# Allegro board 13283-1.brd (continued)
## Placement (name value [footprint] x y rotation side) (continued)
EC9704  SCD1U25V2KX-GP  [C402H22]  147.77 31.95 90 top
EC9705  SCD1U25V2KX-GP  [C402H22]  123.52 148.91 0 bottom
EC9707  SC1KP50V2KX-1GP  [C402H22]  62.43 96.84 180 top
EC9708  SCD1U25V2KX-GP  [C402H22]  108.28 2.99 0 top
EC9709  SC1KP50V2KX-1GP  [C402H22]  113.87 19.37 270 top
EC9710  SC1KP50V2KX-1GP  [C402H22]  118.06 33.6 180 top
EC9711  SC1KP50V2KX-1GP  [C402H22]  152.6 55.57 90 top
EC9712  SCD1U25V2KX-GP  [C402H22]  168.48 70.17 90 top
EC9713  SCD1U25V2KX-GP  [C402H22]  119.07 131.77 90 bottom
EC9714  SC1KP50V2KX-1GP  [C402H22]  119.2 115.51 270 top
EC9715  SCD1U25V2KX-GP  [C402H22]  148.03 96.33 0 top
EC9716  SCD1U25V2KX-GP  [C402H22]  55.19 92.52 270 top
EC9717  SCD1U25V2KX-GP  [C402H22]  86.73 125.76 180 bottom
EC9718  SC1U6D3V2KX-GP  [C402H22]  46.96 2.66 0 top
EC9719  SC1U6D3V2KX-GP  [C402H22]  50.98 2.66 0 top
EC9720  SC1U6D3V2KX-GP  [C402H22]  167.59 10.23 180 top
EC9721  SC1U6D3V2KX-GP  [C402H22]  187.98 7.47 180 bottom
EC9722  SC1U6D3V2KX-GP  [C402H22]  134.66 6.31 180 top
EC9723  SC1U6D3V2KX-GP  [C402H22]  195.91 71.57 90 top
EC9724  SC1U6D3V2KX-GP  [C402H22]  30.81 70.81 180 top
EC9725  SC1U6D3V2KX-GP  [C402H22]  195.27 83.63 270 bottom
EC9726  SC1U6D3V2KX-GP  [C402H22]  152.35 153.23 180 top
EC9727  SC1U6D3V2KX-GP  [C402H22]  193.58 110.21 90 bottom
EC9728  SC1U6D3V2KX-GP  [C402H22]  147.14 130.24 90 bottom
EC9729  SC1U6D3V2KX-GP  [C402H22]  148.79 153.23 0 bottom
EC9730  SC1U6D3V2KX-GP  [C402H22]  189.81 130.24 270 bottom
EC9731  SC1U6D3V2KX-GP  [C402H22]  176.73 69.54 90 bottom
EC9732  SC1U6D3V2KX-GP  [C402H22]  137.38 7.41 0 top
EC9733  SC1U6D3V2KX-GP  [C402H22]  104.43 9.09 0 bottom
EC9734  SC1U6D3V2KX-GP  [C402H22]  138.27 7.41 0 top
EC9735  SC1U6D3V2KX-GP  [C402H22]  35.13 68.75 0 top
EC9736  SC1U6D3V2KX-GP  [C402H22]  51.64 72.2 0 bottom
EC9737  SC1U6D3V2KX-GP  [C402H22]  45.67 35.53 180 top
EC9738  SC1U6D3V2KX-GP  [C402H22]  130.15 3.78 0 top
EC9739  SCD1U10V2KX-5GP  [C402H22]  33.12 20.92 180 top
EC9740  SCD1U25V2KX-GP  [C402H22]  115.39 132.02 180 top
EC9741  SCD1U25V2KX-GP  [C402H22]  158.82 100.65 90 top
EC9742  SCD1U25V2KX-GP  [C402H22]  139.77 113.35 180 top
EC9743  SCD1U10V2KX-5GP  [C402H22]  32.31 20.92 180 top
EC9744  SCD1U10V2KX-5GP  [C402H22]  31.49 20.92 180 top
EC9745  SC1KP50V2KX-1GP  [C402H22]  28.65 7.94 270 bottom
EC9747  SCD1U25V2KX-GP  [C402H22]  127.45 119.19 180 top
EC9748  SCD1U25V2KX-GP  [C402H22]  125.68 127.7 0 bottom
EC9749  SCD1U25V2KX-GP  [C402H22]  143.18 13.89 0 top
ED2901  AZ2025-01H-R7G-GP  [SOD-523-4H28]  23.49 8.41 90 top
ED2902  AZ2025-01H-R7G-GP  [SOD-523-4H28]  23.44 3.62 0 top
ED2903  AZ2025-01H-R7G-GP  [SOD-523-4H28]  18.87 2.99 90 top
ED2904  AZ2025-01H-R7G-GP  [SOD-523-4H28]  23.44 6.55 90 top
ED2905  AZ2025-01H-R7G-GP  [SOD-523-4H28]  23.49 10.22 90 top
F5201  POLYSW-1D1A24V-2-GP  [POLYSW-4633-UH63]  56.08 85.79 0 top
F5203  POLYSW-1D1A24V-GP-U  [POLYSW-4633-UH43]  31.13 74.23 270 top
F5401  POLYSW-1D1A6V-9-GP-U  [POLYSW-2114H30]  18.41 94.2 90 bottom
F6201  POLYSW-D5A6V-1-GP  [POLYSW-2114H50]  126.18 101.54 0 top
FAN1  ETY-CON3-8-GP  [3703K-Q03N-11L]  47.78 92.43 270 bottom
FAN261  APL5606AKI-TRG-GP  [SOIC8H69]  31.95 93.41 270 bottom
G701  GAP-OPEN  [CON2O-U]  114.25 101.92 90 top
GPU1  SUN-S3-XT-GP  [BGA631M23H82]  165.09 117.24 180 bottom
H1  HOLE335R115-GP  [HOLE335R115]  116.1 152.7 0 top
H2  HOLE335R115-GP  [HOLE335R115]  19.9 16.2 0 top
H3  HOLE335R115-GP  [HOLE335R115]  24.8 67.4 0 top
H4  HOLE256R115-GP  [HOLE256R115]  194.9 62.4 0 top
H5  HT85BE85R29-U-5-GP  [HT85BE85R29-U-5]  175.4 5.2 0 top
H6  HT85BE85R29-U-5-GP  [HT85BE85R29-U-5]  197.94 141.4 0 bottom
HDA27  ALC3234-CG-GP  [QFN48J6-G465H40]  35.63 10.74 270 top
HDD1  SKT-SATA7P-15P-159-GP  [127043HR022M25FZR]  198.74 23.03 270 bottom
HDMI1  SKT-HDMI23-97-GP  [SKT-HDMI23-188137]  4.05 86.2 90 bottom
HDT1  PAD-20P-127058-GP  [PAD-20P-127058]  59.76 70.81 270 top
HPMIC1  AUDIO-JK430-GP  [2SJ3080-036111F]  3.5 8.1 90 bottom
IOBD1  PTWO-CON16-2-GP  [196353-16021-3]  184.9 12.65 90 top
KB1  ACES-CON30-10-GP  [FL4S030HT6R300-DT]  183.8 93.86 270 top
KB2  ACES-CON30-10-GP  [FL4S030HT6R300-DT]  194.9 121.9 270 top
KBC24  NPCE285PA0DX-GP  [LQFP128H63]  169.89 29.9 270 top
KBLIT1  ACES-CON4-56-GP  [51575-00441-W01]  133.93 103.06 90 top
L3001  IND-4D7UH-242-GP  [L2520-D820H41]  30.1 40.5 180 bottom
L7504  BLM15BD121SN1D-GP  [L402H22]  163.4 105.22 180 top
L7601  BLM15BD121SN1D-GP  [L402H22]  160.09 103.19 90 bottom
L7603  BLM15BD121SN1D-GP  [L402H22]  164.21 101.97 0 bottom
L7703  BLM15BD121SN1D-GP  [L402H22]  184.22 125.42 0 bottom
L7704  BLM15AG221SN-GP  [L402H24]  176.48 121.35 0 top
L7705  BLM15BD121SN1D-GP  [L402H22]  184.22 127.45 180 bottom
L7706  0R0603-PAD-2-GP-U  [0R0603-PAD-1-U]  170.76 102.56 0 bottom
L7707  0R0603-PAD-2-GP-U  [0R0603-PAD-1-U]  167.71 105.48 180 top
LCD1  ACES-CON40-18-GP  [51540-04001-W01]  37.2 86.7 180 top
LIDSW1  S-5712ACDL1-M3T1U-GP  [SOT23-2D8-123H52]  2.8 73.6 270 top
LOM30  RTL8111G-CGT-1-GP-U1  [QFN32J4-G2D9-U1H36]  36.08 44.35 180 bottom
NOREF  -  []  4.9 -23.3 0 top
NOREF#2  -  []  0 110.96 270 top
NOREF#3  -  []  99.67 3.17 0 top
NOREF#4  *  [unnamed#2]  13.09 161.75 0 top
NOREF#5  *  [unnamed#2]  188.23 155.34 0 top
NOREF#6  -  []  95.96 50.61 0 top
NOREF#7  -  []  96.72 -3.49 0 top
NOREF#8  -  [unnamed#2]  62.23 116.65 0 top
NOREF#9  -  [unnamed#2]  5.32 163.87 0 top
NOREF#10  *  [unnamed#2]  139.65 96.08 0 top
NOREF#11  -  [unnamed#2]  198.19 53.13 0 top
NOREF#12  *  [unnamed#2]  169.36 80.08 0 top
NOREF#13  -  []  -14.81 138.55 0 top
NOREF#14  *  [unnamed#2]  28.78 5.78 0 top
NOREF#15  -  [unnamed#2]  192.53 3.75 0 top
NOREF#16  -  []  15.98 171.2 0 top
NOREF#17  *  [unnamed#2]  206.75 160.37 0 top
NOREF#18  -  [unnamed#2]  18.74 72.33 0 top
NOREF#19  -  []  213.89 52.6 90 top
NOREF#20  *  [unnamed#2]  209.43 10.58 0 top
NOREF#21  -  [unnamed#2]  167.7 154.4 0 top
NOREF#22  -  [unnamed#2]  206.77 165.96 0 top
NOREF#23  -  [unnamed#2]  189.28 164.18 0 top
NOREF#24  *  [unnamed#2]  194.38 7.05 0 top
NOREF#25  *  [unnamed#2]  48.46 24.2 0 top
NOREF#26  -  [unnamed#2]  206.66 -0.48 0 top
NOREF#27  -  [unnamed#2]  20.47 35.2 270 top
NOREF#28  -  []  4.9 -23.3 0 top
NOREF#29  -  []  4.9 -23.3 0 top
NOREF#30  *  [unnamed#2]  56.61 57.17 180 bottom
NOREF#31  -  []  93.04 2.86 180 bottom
NOREF#32  *  [unnamed#2]  188.29 155.39 180 bottom
NOREF#33  *  [unnamed#2]  28.27 37.28 0 bottom
NOREF#34  -  []  113.48 -3.49 180 bottom
NOREF#35  *  [unnamed#2]  24.51 4.11 180 bottom
NOREF#36  -  []  195.27 129.48 180 bottom
NOREF#37  *  [unnamed#2]  120.62 127.96 180 bottom
NOREF#38  *  [unnamed#2]  94.69 142.28 180 bottom
NOREF#39  -  []  66.42 50.16 180 bottom
NOREF#40  *  [unnamed#2]  206.75 160.37 180 bottom
NOREF#41  -  []  81.86 41.47 180 bottom
NOREF#42  *  [unnamed#2]  194.13 7.18 180 bottom
NOREF#43  *  [unnamed#2]  13.09 161.75 180 bottom
NOREF#44  *  [unnamed#2]  209.43 10.58 180 bottom
ODD1  SKT-SATA7P+6P-57-GP-U  [C185A1-11305-L-U]  201.55 76.9 270 bottom
PC4010  SCD47U25V3KX-1GP  [C603H36]  135.58 119.32 0 top
PC4201  SC1U50V5ZY-1-GP-U  [C805H58]  94.94 148.79 180 bottom
PC4202  SCD1U50V3KX-GP  [C603H36]  97.99 148.91 180 bottom
PC4203  SCD01U50V2KX-1GP  [C402H22]  87.2 150.69 90 bottom
PC4204  SCD01U50V2KX-1GP  [C402H22]  87.2 152.47 90 bottom
PC4205  SCD01U50V2KX-1GP  [C402H22]  87.2 151.58 90 bottom
PC4206  SC10U25V5KX-GP  [C805H56]  87.2 149.17 90 bottom
PC4208  SC1U25V3KX-1-GP  [C603H36]  96.09 145.99 180 bottom
PC4209  SCD01U50V2KX-1GP  [C402H22]  110.82 144.34 270 bottom
PC4210  SCD47U6D3V2KX-GP  [C402H22]  110.82 146.88 270 bottom
PC4401  SCD1U25V3KX-GP  [C603H36]  142.67 117.85 90 top
PC4402  SCD1U25V2KX-GP  [C402H22]  138.61 117.21 90 bottom
PC4403  SC1U25V3KX-1-GP  [C603H36]  137.46 118.36 90 bottom
PC4404  SC1U25V3KX-1-GP  [C603H36]  140 118.36 270 bottom
PC4406  SC10U25V5KX-GP  [C805H56]  130.25 125.8 270 bottom
PC4407  SC1U25V3KX-1-GP  [C603H36]  136.34 123.64 90 bottom
PC4408  SC4D7U25V5KX-GP  [C805H54]  130.25 123.89 270 bottom
PC4409  SCD1U50V3KX-GP  [C603H36]  130.25 125.54 90 top
PC4411  SCD047U25V2KX-GP  [C402H22]  134.44 122.12 0 top
PC4412  SCD01U50V2KX-1GP  [C402H22]  141.91 120.39 90 bottom
PC4413  SC3300P50V3KX-1GP  [C603H36]  135.58 121.73 180 top
PC4415  SC10U25V5KX-GP  [C805H56]  141.17 147.06 270 bottom
PC4416  SC10U25V5KX-GP  [C805H56]  141.17 145.23 270 bottom
PC4417  SC10U25V5KX-GP  [C805H56]  141.17 147.39 90 top
PC4418  SC10U25V5KX-GP  [C805H56]  141.17 149.29 90 top
PC4419  SCD1U50V3KX-GP  [C603H36]  141.27 148.71 270 bottom
PC4420  SCD1U25V2KX-GP  [C402H22]  140.28 125.42 180 bottom
PC4421  SCD1U25V2KX-GP  [C402H22]  140.79 126.69 270 bottom
PC4422  SC220P50V2JN-3GP  [C402H22]  141.91 122.17 90 bottom
PC4423  SCD1U25V2KX-GP  [C402H22]  141.17 125.42 180 bottom
PC4425  SCD01U50V2KX-1GP  [C402H22]  135.43 115.56 0 top
PC4426  SC10U25V5KX-GP  [C805H56]  130.25 123.89 90 top
PC4434  SC1U25V3KX-1-GP  [C603H36]  121.61 143.2 0 bottom
PC4501  SC18P50V2JN-1-GP  [C402H22]  130.12 44.14 180 top
PC4502  SC18P50V2JN-1-GP  [C402H22]  131.9 44.14 180 top
PC4510  SCD1U10V2KX-5GP  [C402H22]  120.09 10.61 90 bottom
PC4511  SCD1U50V3KX-GP  [C603H36]  123.64 30.93 90 top
PC4512  SC4D7U25V5KX-GP  [C805H54]  123.64 32.58 90 top
PC4513  SCD1U50V3KX-GP  [C603H36]  126.69 39.57 270 top
PC4514  SC560P50V-GP  [C603]  128.98 29.76 180 top
PC4515  SC4D7U6D3V3KX-GP  [C603H36]  132.15 35.63 0 top
PC4516  SC4D7U6D3V3KX-GP  [C603H36]  135.84 37.91 90 top
PC4517  SC10U25V5KX-GP  [C805H56]  128.01 36.01 0 top
PC4518  SCD1U50V3KX-GP  [C603H36]  129.56 36.14 0 top
PC4519  SCD1U50V3KX-GP  [C603H36]  135.96 39.31 270 top
PC4520  SC1U50V3KX-GP  [C603H32]  133.8 35.63 180 bottom
PC4521  SC560P50V-GP  [C603]  130.88 29.76 180 top
PC4523  SC10U25V5KX-GP  [C805H56]  136.73 32.33 270 top
PC4524  SCD1U50V3KX-GP  [C603H36]  136.47 30.68 270 top
PC4525  SCD1U10V2KX-5GP  [C402H22]  139.27 10.36 270 bottom
PC4526  SC22P50V2JN-4GP  [C402H22]  127.45 44.14 0 top
PC4527  SC22P50V2JN-4GP  [C402H22]  134.95 43.88 270 top
PC4528  SC1U10V2KX-1GP  [C402H22]  135.33 41.72 0 top
PC4601  SC1KP50V2KX-1GP  [C402H22]  108.79 134.82 270 top
PC4603  SC2D2U10V3KX-1GP  [C603H36]  105.48 133.55 180 top
PC4604  SC2D2U10V3KX-1GP  [C603H36]  112.34 138.68 0 bottom
PC4605  SC100P50V2JN-3GP  [C402H22]  111.2 135.7 180 bottom
PC4606  SC47P50V2JN-3GP  [C402H22]  112.09 136.59 0 bottom
PC4609  SC68P50V2JN-1GP  [C402H22]  100.91 138.24 0 top
PC4610  SCD1U10V2KX-5GP  [C402H22]  113.48 135.32 270 bottom
PC4611  SC100P50V2JN-3GP  [C402H22]  101.8 135.7 0 bottom
PC4612  SCD1U10V2KX-5GP  [C402H22]  100.91 136.47 0 bottom
PC4613  SCD1U10V2KX-5GP  [C402H22]  107.39 137.99 0 top
PC4617  SCD1U10V2KX-5GP  [C402H22]  106.5 137.99 0 top
PC4618  SC1U6D3V2ZY-GP  [C402H22]  104.72 137.99 0 top
PC4620  SCD1U10V2KX-4GP  [C402H20]  101.29 138.63 90 bottom
PC4621  SCD1U10V2KX-5GP  [C402H22]  101.29 139.51 90 bottom
PC4622  SCD1U10V2KX-4GP  [C402H20]  108.15 141.67 180 top
PC4623  SC1U25V3KX-1-GP  [C603H36]  117.12 123.84 180 bottom
PC4625  SC1U25V3KX-1-GP  [C603H36]  119.73 118.53 180 bottom
PC4701  SCD1U10V2KX-4GP  [C402H20]  101.29 134.31 270 top
PC4702  SCD1U10V2KX-4GP  [C402H20]  111.2 133.93 180 top
PC4703  SCD1U10V2KX-4GP  [C402H20]  112.09 133.93 180 top
PC4704  SCD1U10V2KX-4GP  [C402H20]  101.29 133.42 270 top
PC4713  SC10U25V5KX-GP  [C805H56]  94.56 129.86 270 bottom
PC4715  SC10U25V5KX-GP  [C805H56]  94.56 129.28 90 top
PC4716  SC10U25V5KX-GP  [C805H56]  110.44 127.83 90 bottom
PC4717  SC10U25V5KX-GP  [C805H56]  110.44 126.03 90 bottom
PC4718  SC10U25V5KX-GP  [C805H56]  110.44 127.83 270 top
PC4719  SC10U25V5KX-GP  [C805H56]  94.56 127.96 270 bottom
PC4720  SCD1U50V3KX-GP  [C603H36]  94.56 127.7 90 top
PC4721  SC10U25V5KX-GP  [C805H56]  110.44 126.03 270 top
PC4722  SCD1U50V3KX-GP  [C603H36]  110.44 124.48 90 bottom
PC4734  SCD1U50V3KX-GP  [C603H36]  107.01 129.48 0 bottom
PC4736  SCD1U50V3KX-GP  [C603H36]  103.71 129.23 0 bottom
PC4742  SC3300P50V3KX-1GP  [C603H36]  100.4 120.21 0 bottom
PC4743  SC3300P50V3KX-1GP  [C603H36]  104.59 117.29 0 bottom
PC4827  SCD1U50V3KX-GP  [C603H36]  161.62 72.97 0 bottom
PC4828  SC4D7U25V5KX-GP  [C805H54]  163.27 72.97 0 bottom
PC4829  SC1U10V2KX-1GP  [C402H22]  171.02 77.03 90 top
PC4830  SC10U25V5KX-GP  [C805H56]  165.17 72.97 0 bottom
PC4831  SC1KP50V2KX-1GP  [C402H22]  175.71 74.49 90 top
PC4832  SC18P50V2JN-1-GP  [C402H22]  175.71 77.16 270 top
PC4833  SCD1U50V3KX-GP  [C603H36]  167.46 74.62 90 bottom
PC4834  SCD1U10V2KX-4GP  [C402H20]  139.9 75.89 0 bottom
PC4838  SC560P50V-GP  [C603]  159.2 74.62 90 top
PC4901  SC1U10V3KX-3GP  [C603H36]  102.46 19.04 180 top
PC4902  SCD01U16V2KX-3GP  [C402H22]  104.59 19.75 180 top
PC4903  SCD1U10V2KX-4GP  [C402H20]  105.48 19.75 180 top
PC4904  SC1U10V3KX-3GP  [C603H36]  106.75 14.6 0 bottom
PC4906  SCD1U10V2KX-5GP  [C402H22]  102.44 11 0 top
PC4909  SC4D7U25V5KX-GP  [C805H54]  96.34 15.44 0 bottom
PC4911  SC4D7U25V5KX-GP  [C805H54]  98.24 15.44 180 top
PC4912  SC10U25V5KX-GP  [C805H56]  100.15 15.44 0 bottom
PC4913  SCD1U50V3KX-GP  [C603H36]  96.59 15.44 0 top
PC4914  SC4D7U25V5KX-GP  [C805H54]  98.24 15.44 0 bottom
PC4915  SCD1U10V2KX-4GP  [C402H20]  110.18 16.71 90 top
PC4916  SC10U6D3V3MX-GP  [C603H38]  109.93 15.31 90 top
PC4917  SC10U6D3V3MX-GP  [C603H38]  109.93 13.4 90 top
PC4918  SCD22U10V2KX-1GP  [C402H22]  107.39 17.59 90 top
PC4919  SCD1U50V3KX-GP  [C603H36]  100.4 14.55 90 top
PC4920  SC4D7U6D3V3KX-GP  [C603H36]  79.47 14.25 0 top
PC4921  SCD1U10V2KX-4GP  [C402H20]  80.86 14.25 0 top
PC4922  SC330P50V2KX-3GP  [C402H22]  94.51 18.15 270 bottom
PC4923  SC22U6D3V5MX-2GP  [C805H58]  79.7 12.77 180 bottom
PC4924  SC22U6D3V5MX-2GP  [C805H58]  77.8 12.77 180 bottom
PC4925  SC22U6D3V5MX-2GP  [C805H58]  81.61 12.77 180 bottom
PC4926  SC22U6D3V5MX-2GP  [C805H58]  83.51 12.77 180 bottom
PC5005  SC1U10V2KX-1GP  [C402H22]  160.86 64.58 0 bottom
PC5010  SC10U6D3V3MX-GP  [C603H38]  148.66 63.7 0 bottom
PC5011  SC10U6D3V3MX-GP  [C603H38]  165.17 58.62 180 bottom
PC5012  SC10U6D3V3MX-GP  [C603H38]  147.27 63.7 0 bottom
PC5013  SC1U6D3V2KX-GP  [C402H22]  165.17 61.92 0 bottom
PC5014  SC22P50V2JN-4GP  [C402H22]  165.17 63.7 180 bottom
PC5015  SC10U6D3V3MX-GP  [C603H38]  166.57 58.62 180 bottom
PC8202  SC2D2U10V3KX-1GP  [C603H36]  152.98 86.81 0 top
PC8203  SC2D2U10V3KX-1GP  [C603H36]  147.01 82.36 0 top
PC8205  SC1U25V3KX-1-GP  [C603H36]  153.49 95.7 180 top
PC8208  SC22P50V2JN-4GP  [C402H22]  147.62 93.67 180 top
PC8209  SC270P50V2JN-2GP  [C402H22]  148.92 93.67 0 top
PC8211  SCD1U10V2KX-4GP  [C402H20]  146.73 93.67 0 top
PC8213  SC1KP50V2KX-1GP  [C402H22]  150.31 82.24 270 top
PC8214  SCD1U10V2KX-4GP  [C402H20]  143.71 86.3 180 bottom
PC8215  14KR2F-GP  [R402H16]  143.33 86.81 270 top
PC8216  SC1U6D3V2ZY-GP  [C402H22]  143.2 91.25 270 top
PC8217  SCD1U10V2KX-4GP  [C402H20]  141.93 90.75 180 top
PC8218  SCD1U10V2KX-4GP  [C402H20]  144.98 93.29 270 top
PC8219  SCD1U10V2KX-4GP  [C402H20]  150.31 83.13 270 top
PC8220  SC10U25V5KX-GP  [C805H56]  158.11 89.6 180 bottom
PC8221  SC10U25V5KX-GP  [C805H56]  156.26 89.6 180 bottom
PC8222  SC10U25V5KX-GP  [C805H56]  154.4 89.6 180 bottom
PC8224  SCD01U50V2KX-1GP  [C402H22]  159.46 89.48 180 bottom
PC8230  SCD1U50V3KX-GP  [C603H36]  154.25 90.11 0 top
PC8232  SC3300P50V3KX-1GP  [C603H36]  162.25 81.86 90 bottom
PC8234  SCD1U10V2KX-4GP  [C402H20]  151.08 93.29 90 top
PC8236  SCD1U10V2KX-4GP  [C402H20]  152.35 95.45 0 top
PC8321  SC10U6D3V3MX-GP  [C603H38]  168.35 57.22 0 bottom
PC8322  SCD01U50V2KX-1GP  [C402H22]  168.86 50.23 180 bottom
PC8323  SC10U6D3V3MX-GP  [C603H38]  162.84 56.41 270 bottom
PC8324  SCD1U10V2KX-5GP  [C402H22]  187.02 112.59 0 bottom
PD4201  P6SBMJ24APT-GP  [D5436AKH97]  100.4 152.57 90 bottom
PD4203  DA3X101F0L-1-GP  [SOT23-2D8-312H56]  118.06 145.74 270 bottom
PD4204  PESD24VS2UT-GP  [SOT-23-10H44]  108.79 152.6 90 top
PD4302  SMF18AT1G-GP  [SOD123FLAKH40]  138.22 143.63 0 bottom
PD4401  SD103AWS-1-GP  [SOD323AKH42]  136.85 125.29 90 bottom
PD4404  1N4148WS-7-F-GP  [SOD323AKH42]  118.44 133.55 270 bottom
PD4505  MMPZ5231BPT-GP  [SOD-323-1UH40]  122.5 37.41 180 top
PD8201  RB551V30-GP  [SOD323AKH38]  149.68 79.57 270 top
PD8307  RB551V30-1-GP  [SOD323AKH44]  169.49 47.57 90 bottom
PD8308  RB551V30-GP  [SOD323AKH38]  190.32 115.77 90 bottom
PG4153  GAP-CLOSE-PWR-3-GP  [GAP-CLOSE-PWR-3]  120.47 14.93 180 bottom
PG4402  GAP-CLOSE-PWR-3-GP  [GAP-CLOSE-PWR-3]  91.51 141.42 0 bottom
PG4403  GAP-CLOSE-PWR-3-GP  [GAP-CLOSE-PWR-3]  91.51 140.15 0 bottom
PG4407  GAP-CLOSE-PWR-3-GP  [GAP-CLOSE-PWR-3]  145.08 122.04 0 top
PG4408  GAP-CLOSE-PWR-3-GP  [GAP-CLOSE-PWR-3]  145.08 121.02 0 top
PG4409  GAP-CLOSE-PWR-3-GP  [GAP-CLOSE-PWR-3]  132.53 142.94 180 bottom
PG4410  GAP-CLOSE-PWR-3-GP  [GAP-CLOSE-PWR-3]  132.53 144.47 180 bottom
PG4411  GAP-CLOSE-PWR-3-GP  [GAP-CLOSE-PWR-3]  139.39 124.02 90 bottom
PG4412  GAP-CLOSE-PWR-3-GP  [GAP-CLOSE-PWR-3]  126.69 125.8 0 bottom
PG4413  GAP-CLOSE-PWR-3-GP  [GAP-CLOSE-PWR-3]  126.69 125.04 0 bottom
PG4414  GAP-CLOSE-PWR-3-GP  [GAP-CLOSE-PWR-3]  126.69 124.27 0 bottom
PG4415  GAP-CLOSE-PWR-3-GP  [GAP-CLOSE-PWR-3]  126.69 123.51 0 bottom
PG4502  GAP-CLOSE-PWR-3-GP  [GAP-CLOSE-PWR-3]  119.33 30.68 180 top
PG4503  GAP-CLOSE-PWR-3-GP  [GAP-CLOSE-PWR-3]  119.33 31.44 180 top
PG4504  GAP-CLOSE-PWR-3-GP  [GAP-CLOSE-PWR-3]  119.33 32.2 180 top
PG4505  GAP-CLOSE-PWR-3-GP  [GAP-CLOSE-PWR-3]  119.33 32.96 180 top
PG4511  GAP-CLOSE-PWR-3-GP  [GAP-CLOSE-PWR-3]  136.34 10.1 90 bottom
PG4512  GAP-CLOSE-PWR-3-GP  [GAP-CLOSE-PWR-3]  135.58 10.1 90 bottom
PG4513  GAP-CLOSE-PWR-3-GP  [GAP-CLOSE-PWR-3]  122.12 10.36 270 bottom
PG4514  GAP-CLOSE-PWR-3-GP  [GAP-CLOSE-PWR-3]  137.11 10.1 90 bottom
PG4515  GAP-CLOSE-PWR-3-GP  [GAP-CLOSE-PWR-3]  140.41 30.42 0 top
PG4516  GAP-CLOSE-PWR-3-GP  [GAP-CLOSE-PWR-3]  140.41 31.18 0 top
PG4517  GAP-CLOSE-PWR-3-GP  [GAP-CLOSE-PWR-3]  140.41 31.95 0 top
PG4518  GAP-CLOSE-PWR-3-GP  [GAP-CLOSE-PWR-3]  140.41 32.71 0 top
PG4519  GAP-CLOSE-PWR-3-GP  [GAP-CLOSE-PWR-3]  140.41 33.47 0 top
PG4520  GAP-CLOSE-PWR-3-GP  [GAP-CLOSE-PWR-3]  140.41 34.23 0 top
PG4521  GAP-CLOSE-PWR-3-GP  [GAP-CLOSE-PWR-3]  140.41 34.99 0 top
PG4522  GAP-CLOSE-PWR-3-GP  [GAP-CLOSE-PWR-3]  122.88 10.36 270 bottom
PG4523  GAP-CLOSE-PWR-3-GP  [GAP-CLOSE-PWR-3]  123.64 10.36 270 bottom
PG4524  GAP-CLOSE-PWR-3-GP  [GAP-CLOSE-PWR-3]  132.53 10.1 90 bottom
PG4525  GAP-CLOSE-PWR-3-GP  [GAP-CLOSE-PWR-3]  124.41 10.36 270 bottom
PG4526  GAP-CLOSE-PWR-3-GP  [GAP-CLOSE-PWR-3]  125.17 10.36 270 bottom
PG4527  GAP-CLOSE-PWR-3-GP  [GAP-CLOSE-PWR-3]  131.77 10.1 90 bottom
PG4528  GAP-CLOSE-PWR-3-GP  [GAP-CLOSE-PWR-3]  133.3 10.1 90 bottom
PG4529  GAP-CLOSE-PWR-3-GP  [GAP-CLOSE-PWR-3]  134.06 10.1 90 bottom
PG4530  GAP-CLOSE-PWR-3-GP  [GAP-CLOSE-PWR-3]  125.93 10.36 270 bottom
PG4531  GAP-CLOSE-PWR-3-GP  [GAP-CLOSE-PWR-3]  134.82 10.1 90 bottom
PG4532  GAP-CLOSE-PWR-3-GP  [GAP-CLOSE-PWR-3]  137.74 14.67 0 bottom
PG4535  GAP-CLOSE-PWR-3-GP  [GAP-CLOSE-PWR-3]  137.87 10.1 90 bottom
PG4701  GAP-CLOSE-PWR-3-GP  [GAP-CLOSE-PWR-3]  95.58 117.04 90 bottom
PG4702  GAP-CLOSE-PWR-3-GP  [GAP-CLOSE-PWR-3]  95.58 114.75 270 bottom
PG4703  GAP-CLOSE-PWR-3-GP  [GAP-CLOSE-PWR-3]  89.61 126.81 180 bottom
PG4704  GAP-CLOSE-PWR-3-GP  [GAP-CLOSE-PWR-3]  89.61 127.58 180 bottom
PG4707  GAP-CLOSE-PWR-3-GP  [GAP-CLOSE-PWR-3]  89.61 129.86 180 bottom
PG4708  GAP-CLOSE-PWR-3-GP  [GAP-CLOSE-PWR-3]  89.61 130.62 180 bottom
PG4709  GAP-CLOSE-PWR-3-GP  [GAP-CLOSE-PWR-3]  89.61 129.1 180 bottom
PG4710  GAP-CLOSE-PWR-3-GP  [GAP-CLOSE-PWR-3]  89.61 128.34 180 bottom
PG4711  GAP-CLOSE-PWR-3-GP  [GAP-CLOSE-PWR-3]  114.63 126.31 0 top
PG4712  GAP-CLOSE-PWR-3-GP  [GAP-CLOSE-PWR-3]  114.63 125.54 0 top
PG4716  GAP-CLOSE-PWR-3-GP  [GAP-CLOSE-PWR-3]  114.63 124.78 0 top
PG4717  GAP-CLOSE-PWR-3-GP  [GAP-CLOSE-PWR-3]  114.63 127.83 0 top
PG4718  GAP-CLOSE-PWR-3-GP  [GAP-CLOSE-PWR-3]  114.63 127.07 0 top
PG4719  GAP-CLOSE-PWR-3-GP  [GAP-CLOSE-PWR-3]  109.42 111.57 270 bottom
PG4720  GAP-CLOSE-PWR-3-GP  [GAP-CLOSE-PWR-3]  109.42 113.86 90 bottom
PG4824  GAP-CLOSE-PWR-3-GP  [GAP-CLOSE-PWR-3]  137.49 72.84 0 bottom
PG4825  GAP-CLOSE-PWR-3-GP  [GAP-CLOSE-PWR-3]  137.49 73.6 0 bottom
PG4826  GAP-CLOSE-PWR-3-GP  [GAP-CLOSE-PWR-3]  137.49 74.36 0 bottom
PG4827  GAP-CLOSE-PWR-3-GP  [GAP-CLOSE-PWR-3]  165.05 70.93 0 bottom
PG4828  GAP-CLOSE-PWR-3-GP  [GAP-CLOSE-PWR-3]  137.49 75.13 0 bottom
PG4830  GAP-CLOSE-PWR-3-GP  [GAP-CLOSE-PWR-3]  137.49 71.32 0 bottom
PG4831  GAP-CLOSE-PWR-3-GP  [GAP-CLOSE-PWR-3]  137.49 72.08 0 bottom
PG4832  GAP-CLOSE-PWR-3-GP  [GAP-CLOSE-PWR-3]  141.3 75.89 270 bottom
PG4834  GAP-CLOSE-PWR-3-GP  [GAP-CLOSE-PWR-3]  165.05 68.65 0 bottom
PG4837  GAP-CLOSE-PWR-3-GP  [GAP-CLOSE-PWR-3]  165.05 69.41 0 bottom
PG4838  GAP-CLOSE-PWR-3-GP  [GAP-CLOSE-PWR-3]  165.05 70.17 0 bottom
PG4901  GAP-CLOSE-PWR-3-GP  [GAP-CLOSE-PWR-3]  109.55 17.98 270 top
PG4902  GAP-CLOSE-PWR-3-GP  [GAP-CLOSE-PWR-3]  108.79 17.98 270 top
PG4903  GAP-CLOSE-PWR-3-GP  [GAP-CLOSE-PWR-3]  97.1 11.24 270 top
PG4904  GAP-CLOSE-PWR-3-GP  [GAP-CLOSE-PWR-3]  97.86 11.24 270 top
PG4905  GAP-CLOSE-PWR-3-GP  [GAP-CLOSE-PWR-3]  98.63 11.24 270 top
PG4906  GAP-CLOSE-PWR-3-GP  [GAP-CLOSE-PWR-3]  96.34 11.24 270 top
PG4907  GAP-CLOSE-PWR-3-GP  [GAP-CLOSE-PWR-3]  76.65 13.66 0 bottom
PG4908  GAP-CLOSE-PWR-3-GP  [GAP-CLOSE-PWR-3]  81.48 18.61 270 top
PG4909  GAP-CLOSE-PWR-3-GP  [GAP-CLOSE-PWR-3]  80.72 18.61 270 top
PG4910  GAP-CLOSE-PWR-3-GP  [GAP-CLOSE-PWR-3]  79.96 18.61 270 top
PG4911  GAP-CLOSE-PWR-3-GP  [GAP-CLOSE-PWR-3]  83 18.61 270 top
PG4913  GAP-CLOSE-PWR-3-GP  [GAP-CLOSE-PWR-3]  76.91 18.61 270 top
PG4914  GAP-CLOSE-PWR-3-GP  [GAP-CLOSE-PWR-3]  77.67 18.61 270 top
PG4915  GAP-CLOSE-PWR-3-GP  [GAP-CLOSE-PWR-3]  78.43 18.61 270 top
PG4916  GAP-CLOSE-PWR-3-GP  [GAP-CLOSE-PWR-3]  79.19 18.61 270 top
PG4917  GAP-CLOSE-PWR-3-GP  [GAP-CLOSE-PWR-3]  82.24 18.61 270 top
PG4918  GAP-CLOSE-PWR-3-GP  [GAP-CLOSE-PWR-3]  83.77 18.61 270 top
PG4919  GAP-CLOSE-PWR-3-GP  [GAP-CLOSE-PWR-3]  84.53 18.61 270 top
PG5009  GAP-CLOSE-PWR-3-GP  [GAP-CLOSE-PWR-3]  168.09 59.5 180 bottom
PG5010  GAP-CLOSE-PWR-3-GP  [GAP-CLOSE-PWR-3]  146.12 59.63 180 bottom
PG5011  GAP-CLOSE-PWR-3-GP  [GAP-CLOSE-PWR-3]  146.12 60.39 180 bottom
PG5012  GAP-CLOSE-PWR-3-GP  [GAP-CLOSE-PWR-3]  146.12 61.16 180 bottom
PG5013  GAP-CLOSE-PWR-3-GP  [GAP-CLOSE-PWR-3]  146.12 61.92 180 bottom
PG5014  GAP-CLOSE-PWR-3-GP  [GAP-CLOSE-PWR-3]  168.09 60.27 180 bottom
PG8203  GAP-CLOSE-PWR-3-GP  [GAP-CLOSE-PWR-3]  157.93 94.68 90 bottom
PG8204  GAP-CLOSE-PWR-3-GP  [GAP-CLOSE-PWR-3]  158.7 94.68 90 bottom
PG8205  GAP-CLOSE-PWR-3-GP  [GAP-CLOSE-PWR-3]  159.46 94.68 90 bottom
PG8206  GAP-CLOSE-PWR-3-GP  [GAP-CLOSE-PWR-3]  154.12 94.68 90 bottom
PG8207  GAP-CLOSE-PWR-3-GP  [GAP-CLOSE-PWR-3]  154.89 94.68 90 bottom
PG8208  GAP-CLOSE-PWR-3-GP  [GAP-CLOSE-PWR-3]  155.65 94.68 90 bottom
PG8209  GAP-CLOSE-PWR-3-GP  [GAP-CLOSE-PWR-3]  156.41 94.68 90 bottom
PG8210  GAP-CLOSE-PWR-3-GP  [GAP-CLOSE-PWR-3]  157.17 94.68 90 bottom
PG8219  GAP-CLOSE-PWR-3-GP  [GAP-CLOSE-PWR-3]  171.9 88.84 180 bottom
PG8220  GAP-CLOSE-PWR-3-GP  [GAP-CLOSE-PWR-3]  174.19 88.84 0 bottom
PG8316  GAP-CLOSE-PWR-3-GP  [GAP-CLOSE-PWR-3]  142.44 104.59 0 bottom
PG8317  GAP-CLOSE-PWR-3-GP  [GAP-CLOSE-PWR-3]  144.35 101.29 0 bottom
PG8318  GAP-CLOSE-PWR-3-GP  [GAP-CLOSE-PWR-3]  144.35 100.53 0 bottom
PG8319  GAP-CLOSE-PWR-3-GP  [GAP-CLOSE-PWR-3]  144.35 99.76 0 bottom
PL4401  IND-5D6UH-45-GP  [L686647H119]  130.35 137.15 90 bottom
PL4501  IND-3D3UH-57GP  [L736630H119]  124.53 23.31 0 bottom
PL4502  IND-2D2UH-46-GP-U  [L736630-MH119]  135.71 23.44 180 bottom
PL4701  IND-D36UH-35-GP  [L7066-1830-UH158]  95.58 115.89 180 bottom
PL4702  IND-D36UH-35-GP  [L7066-1830-UH158]  109.42 112.72 180 bottom
PL4802  IND-2D2UH-46-GP-U  [L736630-MH119]  150.7 72.59 90 bottom
PL4902  COIL-D68UH-5-GP  [L736630H119]  89.1 14.72 90 bottom
PL5002  IND-2D2UH-46-GP-U  [L736630-MH119]  154.25 60.39 90 bottom
PL8201  IND-D36UH-35-GP  [L7066-1830-UH158]  173.05 88.84 270 bottom
PQ4201  FDV301N-NL-GP  [SOT23DGS2D4H44]  112.47 145.74 90 top
PQ4202  CH3904PT-GP  [SOT23CBE2D6H46]  113.87 145.86 270 bottom
PQ4203  2N7002KDW-GP  [SOT-363H44]  109.42 150.18 180 bottom
PQ4204  PDTC124EU-1-GP  [SOT323CBE2D2H44]  108.15 147.39 90 top
PQ4205  PDTA124EU-1-GP  [SOT323CBE2D2H44]  108.15 144.34 90 top
PQ4206  2N7002KDW-GP  [SOT-363H44]  106.25 150.18 180 bottom
PQ4208  2N7002K-2-GP  [SOT23DGS2D4H44]  107.41 146.37 270 bottom
PQ4402  2N7002KDW-GP  [SOT-363H44]  92.28 146.37 0 bottom
PQ4407  2N7002KDW-GP  [SOT-363H44]  143.08 116.4 270 bottom
PQ4408  2N7002KDW-GP  [SOT-363H44]  133.02 115.94 90 top
PQ4409  MMBT3906-4-GP  [SOT23CBE2D4H44]  118.06 136.47 90 bottom
PQ4410  2N7002KDW-GP  [SOT-363H44]  120.72 140.15 180 bottom
PQ4501  2N7002KDW-GP  [SOT-363H44]  137.61 45.15 0 top
PQ4502  2N7002KDW-GP  [SOT-363H44]  125.3 35.63 270 top
PQ4601  2N7002KDW-GP  [SOT-363H44]  120.47 123 90 bottom
PQ8201  2N7002K-2-GP  [SOT23DGS2D4H44]  157.63 93.51 0 top
PQ8305  2N7002KDW-GP  [SOT-363H44]  144.98 78.3 90 top
PQ8314  2N7002KDW-GP  [SOT-363H44]  174.57 48.2 90 bottom
PQ8317  2N7002K-2-GP  [SOT23DGS2D4H44]  174.57 51.63 180 bottom
PQ8318  AO4468L-GP  [SOIC8H69]  164.79 52.9 270 bottom
PQ8319  2N7002KDW-GP  [SOT-363H44]  190.57 112.97 270 bottom
PQ8320  DMP2130L-7-GP  [SOT23DGS2D4H48]  184.6 112.34 270 bottom
PR3622  10KR2J-3-GP  [R402H16]  138.88 64.2 90 top
PR4202  15KR2F-GP  [R402H16]  109.8 149.42 270 top
PR4203  10KR2J-3-GP  [R402H16]  113.74 143.32 90 top
PR4204  2K2R2J-2-GP  [R402H16]  118.06 143.32 90 bottom
PR4205  33R2J-2-GP  [R402H16]  114.88 145.61 0 top
PR4207  240KR3-GP  [R603H22]  96.59 148.91 180 bottom
PR4208  47KR3J-L-GP  [R603H22]  94.69 145.99 180 bottom
PR4209  100KR2J-1-GP  [R402H16]  109.8 150.31 90 top
PR4210  1KR2J-1-GP  [R402H16]  107.01 152.47 270 bottom
PR4211  10KR2J-3-GP  [R402H16]  109.93 152.47 270 bottom
PR4212  100KR2J-1-GP  [R402H16]  102.31 147.13 0 bottom
PR4213  100KR2J-1-GP  [R402H16]  103.2 147.13 180 bottom
PR4214  3K3R6J-GP  [R1206H28]  101.67 149.17 270 bottom
PR4215  1KR2J-1-GP  [R402H16]  110.44 145.61 0 bottom
PR4216  100KR2J-1-GP  [R402H16]  111.33 145.61 180 bottom
PR4217  0R0603-PAD-2-GP-U  [0R0603-PAD-1-U]  107.64 150.06 90 top
PR4218  100KR2J-1-GP  [R402H16]  110.82 147.77 270 bottom
PR4401  10KR2F-2-GP  [R402H16]  92.66 143.58 180 bottom
PR4402  D01R3721F-GP-U  [R3720H40]  89.23 140.78 180 bottom
PR4403  100KR2J-1-GP  [R402H16]  91.77 143.58 0 bottom
PR4404  3KR5J-GP  [R805H24]  91.26 149.17 270 bottom
PR4405  470KR2J-2-GP  [R402H16]  117.29 141.04 270 bottom
PR4406  0R2J-2-GP  [R402H16]  138.61 116.32 270 bottom
PR4407  309KR2F-GP  [R402H16]  144.57 119.24 270 top
PR4408  10R5J-GP  [R805H24]  133.42 119.7 90 top
PR4409  0R3J-0-U-GP  [R603H22]  134.69 123.64 270 top
PR4411  102KR2F-GP  [R402H16]  141.02 117.21 180 top
PR4412  3K3R2F-2-GP  [R402H16]  139.14 136.34 90 top
PR4413  84K5R2F-GP  [R402H16]  140.64 120.77 0 bottom
PR4414  3D3MR2J-GP  [R402H16]  140 118.61 90 top
PR4415  3K3R2F-2-GP  [R402H16]  143.2 138.5 180 top
PR4416  D01R3721F-GP-U  [R3720H40]  130.25 143.71 0 bottom
PR4417  100KR2J-1-GP  [R402H16]  144.32 123.82 270 top
PR4418  0R2J-2-GP  [R402H16]  145.21 125.59 270 top
PR4419  100KR2J-1-GP  [R402H16]  137.84 114.04 270 top
PR4420  7D5R2F-GP  [R402H16]  141.17 126.31 180 top
PR4421  10R2F-L-GP  [R402H14]  140.28 126.31 180 top
PR4422  0R0402-PAD-2-GP  [0R0402-PAD-1]  144.57 120.13 90 top
PR4423  59KR2F-GP  [R402H16]  144.32 122.93 90 top
PR4424  8K45R2F-2-GP  [R402H16]  141.91 123.05 90 bottom
PR4425  100KR2J-1-GP  [R402H16]  143.36 116.3 180 top
PR4426  0R0402-PAD-2-GP  [0R0402-PAD-1]  130.73 115.21 0 top
PR4427  66K5R2F-GP  [R402H16]  140.13 117.21 180 top
PR4428  100KR2J-1-GP  [R402H16]  137.46 115.43 0 top
PR4429  150KR2F-L-GP  [R402H16]  139.24 117.21 0 top
PR4430  100KR2J-1-GP  [R402H16]  137.46 117.21 180 top
PR4431  47KR2F-GP  [R402H16]  141.91 121.28 90 bottom
PR4432  120KR2F-L-GP  [R402H16]  138.22 118.61 270 top
PR4433  120KR2F-L-GP  [R402H16]  142.29 118.99 90 top
PR4434  100KR2J-1-GP  [R402H16]  142.36 116.3 180 top
PR4435  10KR2F-2-GP  [R402H16]  145.74 124.27 180 top
PR4436  120KR2F-L-GP  [R402H16]  136.6 114.5 180 top
PR4437  160KR2F-GP  [R402H16]  136.19 117.21 270 top
PR4438  100KR2J-1-GP  [R402H16]  138.35 117.21 0 top
PR4439  10KR2F-2-GP  [R402H16]  146.63 124.27 180 top
PR4464  680KR2J-GP  [R402H16]  120.98 135.7 90 bottom
PR4466  0R2J-2-GP  [R402H16]  118.69 140.15 0 bottom
PR4467  1MR2J-1-GP  [R402H16]  117.8 139.77 0 bottom
PR4468  0R2J-2-GP  [R402H16]  121.23 132.91 0 bottom
PR4469  100KR2J-1-GP  [R402H16]  116.91 139.77 180 bottom
PR4470  100KR2F-L1-GP  [R402H16]  119.33 143.07 0 bottom
PR4473  10KR2F-2-GP  [R402H16]  120.98 144.85 90 bottom
PR4475  0R2J-2-GP  [R402H16]  120.47 137.1 0 bottom
PR4476  0R2J-2-GP  [R402H16]  121.36 137.1 0 bottom
PR4501  10KR2J-3-GP  [R402H16]  138.38 42.36 180 top
PR4502  200KR2J-L1-GP  [R402H16]  137.49 42.36 0 top
PR4503  169KR2F-1-GP  [R402H16]  131.01 44.14 180 top
PR4504  365KR2F-GP  [R402H16]  132.79 44.14 0 top
PR4505  2D2R5F-2-GP  [R805H24]  128.98 26 180 top
PR4506  6K65R2F-GP  [R402H16]  128.34 44.14 0 top
PR4507  10KR2F-2-GP  [R402H16]  129.23 44.14 180 top
PR4508  2D2R2J-GP  [R402H16]  126.31 40.71 90 top
PR4509  100KR2J-1-GP  [R402H16]  126.69 41.72 90 top
PR4510  0R0402-PAD-2-GP  [0R0402-PAD-1]  135.71 36.77 90 top
PR4511  0R0402-PAD-2-GP  [0R0402-PAD-1]  130.63 36.39 180 top
PR4513  2D2R2J-GP  [R402H16]  136.22 40.45 90 top
PR4514  200KR2F-L-GP  [R402H16]  132.66 35.76 180 bottom
PR4515  100KR2F-L1-GP  [R402H16]  132.03 41.34 180 bottom
PR4516  39KR2F-GP  [R402H16]  131.77 35.76 180 bottom
PR4517  2D2R5F-2-GP  [R805H24]  130.88 26 180 top
PR4518  15KR2F-GP  [R402H16]  134.95 42.99 270 top
PR4519  10KR2F-2-GP  [R402H16]  133.68 44.14 180 top
PR4520  40K2R2F-GP  [R402H16]  124.03 38.93 0 top
PR4521  750KR2F-GP  [R402H16]  124.66 37.66 90 top
PR4522  100KR2F-L1-GP  [R402H16]  120.98 37.41 180 top
PR4603  0R0402-PAD-2-GP  [0R0402-PAD-1]  106.63 133.16 180 top
PR4604  10R3J-3-GP  [R603H22]  113.61 138.68 0 bottom
PR4607  0R0402-PAD-2-GP  [0R0402-PAD-1]  113.87 136.59 180 bottom
PR4608  10KR2F-2-GP  [R402H16]  112.98 136.59 180 bottom
PR4609  49K9R2F-L-GP  [R402H16]  112.85 136.97 90 top
PR4610  100KR2F-L1-GP  [R402H16]  112.85 136.09 90 top
PR4612  10R2F-L-GP  [R402H14]  90.62 83.38 270 top
PR4613  0R0402-PAD-2-GP  [0R0402-PAD-1]  113.99 134.43 270 bottom
PR4615  0R0402-PAD-2-GP  [0R0402-PAD-1]  114.72 136.59 0 bottom
PR4620  100KR2F-L1-GP  [R402H16]  99.64 138.63 270 top
PR4621  11KR2F-L-GP  [R402H16]  99.64 137.74 90 top
PR4622  10KR2F-2-GP  [R402H16]  101.42 136.85 270 top
PR4623  0R0402-PAD-2-GP  [0R0402-PAD-1]  101.29 135.58 0 top
PR4624  0R0402-PAD-2-GP  [0R0402-PAD-1]  103.71 141.67 180 bottom
PR4625  0R0402-PAD-2-GP  [0R0402-PAD-1]  104.59 141.67 180 bottom
PR4626  0R0402-PAD-2-GP  [0R0402-PAD-1]  99.64 136.85 270 top
PR4627  10R2F-L-GP  [R402H14]  90.62 81.02 90 top
PR4628  0R0402-PAD-2-GP  [0R0402-PAD-1]  105.48 141.93 180 bottom
PR4629  0R2J-2-GP  [R402H16]  108.15 141.67 0 bottom
PR4630  0R0402-PAD-2-GP  [0R0402-PAD-1]  106.37 141.67 180 bottom
PR4631  0R0402-PAD-2-GP  [0R0402-PAD-1]  108.28 137.99 180 top
PR4632  0R0402-PAD-2-GP  [0R0402-PAD-1]  99.67 135.93 90 bottom
PR4633  10R2F-L-GP  [R402H14]  90.62 82.24 90 top
PR4634  14KR2F-GP  [R402H16]  109.04 141.67 0 bottom
PR4636  0R2J-2-GP  [R402H16]  107.26 141.67 0 bottom
PR4637  0R0402-PAD-2-GP  [0R0402-PAD-1]  112.09 140.4 90 bottom
PR4638  0R0402-PAD-2-GP  [0R0402-PAD-1]  105.61 137.99 180 top
PR4639  0R0402-PAD-2-GP  [0R0402-PAD-1]  108.79 133.93 270 top
PR4645  37K4R2F-1-GP  [R402H16]  101.29 137.74 90 bottom
PR4646  15K4R2F-GP  [R402H16]  101.98 141.67 0 bottom
PR4648  2D2R2F-GP  [R402H16]  102.82 141.67 180 bottom
PR4649  0R0402-PAD-2-GP  [0R0402-PAD-1]  101.42 143.96 90 bottom
PR4651  10KR2F-2-GP  [R402H16]  110.54 131.03 0 bottom
PR4652  10KR2F-2-GP  [R402H16]  116.05 132.1 90 bottom
PR4653  130KR2F-GP  [R402H16]  107.26 141.67 180 top
PR4654  130KR2F-GP  [R402H16]  105.48 141.67 180 top
PR4655  130KR2F-GP  [R402H16]  104.59 141.67 180 top
PR4656  300R2F-GP  [R402H16]  102.82 141.67 180 top
PR4657  12K7R2F-GP  [R402H16]  99.01 138.63 90 bottom
PR4658  22KR2F-GP  [R402H16]  100.15 141.67 0 bottom
PR4659  39KR2F-GP  [R402H16]  99.01 139.51 90 bottom
PR4660  28K7R2F-GP  [R402H16]  101.04 140.78 180 bottom
PR4661  0R0402-PAD-2-GP  [0R0402-PAD-1]  98.68 140.33 90 bottom
PR4662  0R0402-PAD-2-GP  [0R0402-PAD-1]  99.26 141.67 0 bottom
PR4663  130KR2F-GP  [R402H16]  106.37 141.67 0 top
PR4664  1KR2F-3-GP  [R402H16]  99.01 137.76 90 bottom
PR4665  115KR2F-GP  [R402H16]  120.29 120.18 90 bottom
PR4666  4D7R2F-GP  [R402H16]  120.85 118.74 180 bottom
PR4667  4D7R2F-GP  [R402H16]  118.21 123.54 0 bottom
PR4668  113KR2F-1-GP  [R402H16]  118.64 124.99 270 bottom
PR4669  210R2F-L-GP  [R402H16]  109.04 143.45 0 bottom
PR4670  124KR2F-GP  [R402H16]  111.45 143.07 90 bottom
PR4671  1KR2F-3-GP  [R402H16]  109.93 141.67 180 bottom
PR4672  33KR2F-GP  [R402H16]  114.12 141.29 90 bottom
PR4673  750R2F-GP  [R402H16]  111.33 141.29 90 bottom
PR4674  100KR2F-L1-GP  [R402H16]  108.79 136.59 90 top
PR4675  453R2F-1-GP  [R402H16]  114.12 142.18 270 bottom
PR4676  6K2R2F-GP  [R402H16]  111.33 142.18 270 bottom
PR4677  NTC-100K-10-GP-U  [NTC-402H22-U]  91.23 116.91 180 bottom
PR4678  NTC-100K-10-GP-U  [NTC-402H22-U]  113.74 113.61 180 bottom
PR4679  0R0402-PAD-2-GP  [0R0402-PAD-1]  111.83 130.67 270 bottom
PR4680  0R2J-2-GP  [R402H16]  113.13 131.16 180 bottom
PR4681  130KR2F-GP  [R402H16]  103.71 141.67 0 top
PR4682  0R2J-2-GP  [R402H16]  120.44 124.99 90 bottom
PR4683  0R2J-2-GP  [R402H16]  120.29 121.05 90 bottom
PR4701  0R3J-6-GP  [R603H22]  102.44 129.23 180 bottom
PR4702  0R3J-6-GP  [R603H22]  108.28 129.48 180 bottom
PR4705  3KR2F-GP  [R402H16]  100.91 134.69 180 bottom
PR4706  10KR2F-2-GP  [R402H16]  100.02 133.93 180 bottom
PR4707  910R2F-1-GP  [R402H16]  101.29 133.42 90 bottom
PR4708  750R2F-GP  [R402H16]  111.58 134.43 270 bottom
PR4709  1R5F-1-GP  [R805H24]  100.4 117.54 0 bottom
PR4710  1R5F-1-GP  [R805H24]  104.59 114.62 0 bottom
PR4711  10KR2F-2-GP  [R402H16]  111.58 133.55 270 bottom
PR4712  3KR2F-GP  [R402H16]  111.58 132.66 90 bottom
PR4817  105KR2F-1-GP  [R402H16]  175.71 72.61 270 top
PR4819  0R0402-PAD-2-GP  [0R0402-PAD-1]  175.71 73.42 270 top
PR4820  2D2R3-1-U-GP  [R603H22]  167.46 73.22 90 bottom
PR4821  0R0402-PAD-2-GP  [0R0402-PAD-1]  171.96 71.95 270 top
PR4822  10KR2F-2-GP  [R402H16]  175.71 76.27 270 top
PR4823  26K1R2F-2-GP  [R402H16]  175.71 75.38 90 top
PR4824  470KR2F-GP  [R402H16]  173.17 77.03 270 top
PR4835  10KR2J-3-GP  [R402H16]  171.96 71.06 90 top
PR4837  2D2R5F-2-GP  [R805H24]  156.41 74.62 90 top
PR4901  30K1R2F-L-GP  [R402H16]  103.71 19.75 180 top
PR4902  133KR2F-GP  [R402H16]  106.12 10.1 0 top
PR4903  10KR2F-2-GP  [R402H16]  104.98 18.48 270 top
PR4904  20KR2F-L-GP  [R402H16]  108.4 10.99 270 top
PR4905  2D2R3-1-U-GP  [R603H22]  100.4 13.15 270 top
PR4906  0R0402-PAD-2-GP  [0R0402-PAD-1]  104.21 21.02 90 top
PR4907  0R0402-PAD-2-GP  [0R0402-PAD-1]  101.58 11 180 top
PR4908  1KR2F-3-GP  [R402H16]  107.01 10.1 0 top
PR4910  0R0402-PAD-2-GP  [0R0402-PAD-1]  103.83 10.86 270 top
PR4911  0R0603-PAD-2-GP-U  [0R0603-PAD-1-U]  106.75 19.5 180 top
PR4912  2D2R5F-2-GP  [R805H24]  94.51 15.3 0 bottom
PR5009  102KR2F-GP  [R402H16]  166.06 63.7 180 bottom
PR5010  0R0402-PAD-2-GP  [0R0402-PAD-1]  161.74 64.58 180 bottom
PR5011  100KR2F-L1-GP  [R402H16]  159.97 64.58 180 bottom
PR5012  2D2R2F-GP  [R402H16]  166.06 61.03 0 bottom
PR5013  51KR2F-L-GP  [R402H16]  164.28 63.7 0 bottom
PR8201  10KR2F-2-GP  [R402H16]  151.08 94.18 90 top
PR8202  0R0402-PAD-2-GP  [0R0402-PAD-1]  154.12 86.94 0 top
PR8203  10R3J-3-GP  [R603H22]  145.74 82.36 0 top
PR8204  115KR2F-GP  [R402H16]  155.27 93.84 180 top
PR8205  4D7R2F-GP  [R402H16]  154.63 95.57 180 top
PR8206  0R2J-2-GP  [R402H16]  153.24 93.67 180 top
PR8214  499KR2F-1-GP  [R402H16]  147.14 93.67 0 bottom
PR8215  9K76R2F-1-GP  [R402H16]  148.03 93.67 180 bottom
PR8216  10KR2F-2-GP  [R402H16]  148.92 93.67 0 bottom
PR8217  0R0402-PAD-2-GP  [0R0402-PAD-1]  149.81 93.67 0 bottom
PR8220  0R0402-PAD-2-GP  [0R0402-PAD-1]  161.03 115.41 270 top
PR8222  0R0402-PAD-2-GP  [0R0402-PAD-1]  161.03 114.57 270 top
PR8227  0R2J-2-GP  [R402H16]  141.93 86.3 180 bottom
PR8228  0R0402-PAD-2-GP  [0R0402-PAD-1]  142.82 86.3 180 bottom
PR8229  15KR2F-GP  [R402H16]  146.25 93.67 0 bottom
PR8230  0R0402-PAD-2-GP  [0R0402-PAD-1]  149.04 82.75 0 top
PR8231  100KR2F-L1-GP  [R402H16]  148.16 82.75 180 top
PR8232  124KR2F-GP  [R402H16]  140.59 85.92 90 top
PR8233  1KR2D-1-GP  [R402H16]  143.33 85.92 90 top
PR8234  210R2F-L-GP  [R402H16]  141.35 86.94 270 top
PR8235  1K8R2F-GP  [R402H16]  143.2 94.18 90 top
PR8237  2D2R2F-GP  [R402H16]  143.2 92.14 90 top
PR8238  33KR2F-GP  [R402H16]  140.59 85.03 90 top
PR8239  750R2F-GP  [R402H16]  143.33 85.03 90 top
PR8240  6K2R2F-GP  [R402H16]  143.33 84.14 270 top
PR8241  453R2F-1-GP  [R402H16]  142.44 83.23 270 top
PR8242  22KR2F-GP  [R402H16]  143.58 95.45 180 top
PR8244  NTC-100K-10-GP-U  [NTC-402H22-U]  172.79 93.21 90 bottom
PR8245  30KR2F-GP  [R402H16]  144.98 94.18 90 top
PR8246  10KR2F-2-GP  [R402H16]  151.2 81.35 270 top
PR8248  4K7R2F-GP  [R402H16]  143.71 82.75 180 top
PR8250  10KR2F-2-GP  [R402H16]  152.73 84.78 180 top
PR8251  10KR2F-2-GP  [R402H16]  143.08 87.7 90 top
PR8252  10KR2F-2-GP  [R402H16]  143.08 88.59 90 top
PR8253  10KR2F-2-GP  [R402H16]  143.08 89.48 90 top
PR8254  4K7R2F-GP  [R402H16]  143.2 90.37 90 top
PR8255  0R0402-PAD-2-GP  [0R0402-PAD-1]  144.47 95.45 180 top
PR8256  10KR2F-2-GP  [R402H16]  143.2 90.37 90 bottom
PR8257  10KR2F-2-GP  [R402H16]  143.08 87.7 90 bottom
PR8259  0R2J-2-GP  [R402H16]  153.74 92.02 270 top
PR8260  1R5F-1-GP  [R805H24]  165.05 81.73 90 bottom
PR8263  3KR2F-GP  [R402H16]  150.7 95.45 0 top
PR8265  750R2F-GP  [R402H16]  152.35 93.67 180 top
PR8269  0R0402-PAD-2-GP  [0R0402-PAD-1]  153.87 83.38 270 top
PR8270  0R0402-PAD-2-GP  [0R0402-PAD-1]  143.08 89.48 90 bottom
PR8271  0R0402-PAD-2-GP  [0R0402-PAD-1]  143.08 88.59 90 bottom
PR8273  0R0402-PAD-2-GP  [0R0402-PAD-1]  153.62 84.78 0 top
PR8274  0R0402-PAD-2-GP  [0R0402-PAD-1]  144.6 82.75 0 top
PR8275  0R0402-PAD-2-GP  [0R0402-PAD-1]  153.87 82.49 90 top
PR8313  100KR2J-1-GP  [R402H16]  142.69 78.05 180 top
PR8316  10R2J-2-GP  [R402H14]  145.87 80.33 270 top
PR8328  0R0402-PAD-2-GP  [0R0402-PAD-1]  170.56 50.61 180 bottom
PR8341  100KR2J-1-GP  [R402H16]  176.86 49.42 0 bottom
PR8344  10R2J-2-GP  [R402H14]  176.86 53.54 180 bottom
PR8345  0R0402-PAD-2-GP  [0R0402-PAD-1]  171.9 49.47 270 bottom
PR8347  10MR2J-L-GP  [R402H16]  169.75 50.23 0 bottom
PR8348  330KR2J-L1-GP  [R402H16]  165.55 48.96 270 bottom
PR8349  10KR2J-3-GP  [R402H16]  187.91 113.86 0 bottom
PR8350  470R2J-2-GP  [R402H16]  184.1 114.62 90 bottom
PR8351  0R2J-2-GP  [R402H16]  184.6 110.05 90 bottom
PR8352  10KR2J-3-GP  [R402H16]  187.91 110.69 180 bottom
PT4501  SE220U6D3VM-38-GP  [SE361414H178]  120.09 14.93 90 bottom
PT4502  SE220U6D3VM-38-GP  [SE361414H178]  138.12 14.67 270 bottom
PT4701  SE330U2D5VM-14-GP  [SE361414H178]  79.7 104.34 90 bottom
PT4702  SE330U2VDM-L-GP  [CT7343H83]  86.05 113.73 0 bottom
PT4703  SE330U2VDM-L-GP  [CT7343H83]  118.44 109.8 90 top
PT4704  SE330U2D5VM-14-GP  [SE361414H178]  118.9 110.15 270 bottom
PT4705  SE68U25VM-3-GP  [SE341413H241]  92.63 135.02 270 bottom
PT4803  SE330U2D5VM-14-GP  [SE361414H178]  142.06 70.3 180 bottom
PT8204  SE330U2D5VM-14-GP  [SE361414H178]  182.45 92.09 270 bottom
PT8205  SE330U2D5VM-14-GP  [SE361414H178]  182.45 84.45 270 bottom
PU4201  AON7401-GP  [PPAK-8P-3232H36]  90.12 152.6 270 bottom
PU4402  AON7401-GP  [PPAK-8P-3232H36]  88.34 146.25 180 bottom
PU4403  AON7401-GP  [PPAK-8P-3232H36]  128.95 147.95 90 bottom
PU4404  BQ24727RGRR-1-GP  [QFN20G3D5-G2D15H40]  140 122.17 180 top
PU4405  SIS412DN-T1-GE3-GP  [PPAK-8P-2H45]  128.45 129.02 0 bottom
PU4406  SIS412DN-T1-GE3-GP  [PPAK-8P-2H45]  133.02 130.55 180 bottom
PU4501  RT8230BGQW-GP  [QFN20-G1D75H32]  131.26 40.07 0 top
PU4502  SIS412DN-T1-GE3-GP  [PPAK-8P-2H45]  121.36 28.01 0 top
PU4503  SIS412DN-T1-GE3-GP  [PPAK-8P-2H45]  125.8 26.48 180 top
PU4504  SIS412DN-T1-GE3-GP  [PPAK-8P-2H45]  138.5 28.01 0 top
PU4505  SIS780DN-T1-GE3-GP  [PPAK-8P-2H45]  134.06 26.48 180 top
PU4601  RT8179CGQW-GP  [QFN40-G3D5H32]  106.5 135.58 270 bottom
PU4701  FDMS3600-02-RJK0215-COLAY-GP  [PPAK-8P-G5324H44-COLAY]  95.58 123.89 90 bottom
PU4702  FDMS3600-02-RJK0215-COLAY-GP  [PPAK-8P-G5324H44-COLAY]  95.58 123.89 270 top
PU4703  FDMS3600-02-RJK0215-COLAY-GP  [PPAK-8P-G5324H44-COLAY]  109.42 120.72 270 bottom
PU4704  FDMS3600-02-RJK0215-COLAY-GP  [PPAK-8P-G5324H44-COLAY]  109.42 120.72 90 top
PU4805  SIS412DN-T1-GE3-GP  [PPAK-8P-2H45]  157.43 75.25 270 bottom
PU4806  RT8237CZQW-2-GP  [DFN10G3-G265175H32]  171.78 74.49 270 top
PU4808  SIS412DN-T1-GE3-GP  [PPAK-8P-2H45]  158.95 70.81 90 bottom
PU4901  TPS51716RUKR-GP  [QFN20-G1D75H32]  105.23 14.55 270 top
PU4902  SIS412DN-T1-GE3-GP  [PPAK-8P-2H45]  93.93 13.4 270 top
PU4903  SIS780DN-T1-GE3-GP  [PPAK-8P-2H45]  92.4 17.98 90 top
PU5002  RT8068AZQWID-GP-U  [DFN10G3-G265175H32]  161.87 60.77 270 bottom
PU8202  RT8179CGQW-GP  [QFN40-G3D5H32]  148.66 87.95 0 top
PU8203  SIRA14DP-T1-GE3-GP  [PPAK-5PH45]  163.01 92.27 270 bottom
PU8205  SIRA06DP-T1-GE3-GP  [PPAK-5PH45]  165.05 85.79 90 bottom
Q403  2N7002KDW-GP  [SOT-363H44]  74.37 79.57 90 bottom
Q601  2N7002KDW-GP  [SOT-363H44]  123.52 90.24 90 bottom
Q603  2N7002KDW-GP  [SOT-363H44]  117.68 92.65 270 bottom
Q701  2N7002K-2-GP  [SOT23DGS2D4H44]  111.58 100.65 270 top
Q2401  2N7002K-2-GP  [SOT23DGS2D4H44]  184.85 35.39 270 top
Q2402  DMP2130L-7-GP  [SOT23DGS2D4H48]  155.12 32.04 0 top
Q2403  2N7002K-2-GP  [SOT23DGS2D4H44]  151.52 32.05 180 top
Q2404  MMBT3906-4-GP  [SOT23CBE2D4H44]  154.6 26.64 90 top
Q2505  2N7002K-2-GP  [SOT23DGS2D4H44]  51 12.64 180 bottom
Q2601  2N7002KDW-GP  [SOT-363H44]  62.45 84.95 90 top
Q2602  2N7002K-2-GP  [SOT23DGS2D4H44]  156.72 21.07 90 top
Q2603  CH3904PT-GP  [SOT23CBE2D6H46]  50.48 46.23 0 top
Q2901  2N7002K-2-GP  [SOT23DGS2D4H44]  22.17 8.32 0 bottom
Q3001  2N7002K-2-GP  [SOT23DGS2D4H44]  44.52 51.5 180 top
Q3002  CH3904PT-GP  [SOT23CBE2D6H46]  40.71 42.61 0 top
Q3003  CH3904PT-GP  [SOT23CBE2D6H46]  40.97 37.96 90 top
Q3004  DMP2130L-7-GP  [SOT23DGS2D4H48]  39.19 48.84 90 top
Q5401  CH3904PT-GP  [SOT23CBE2D6H46]  46.05 55.69 270 bottom
Q5402  2N7002KDW-GP  [SOT-363H44]  18.97 91.3 90 bottom
Q5403  2N7002K-2-GP  [SOT23DGS2D4H44]  22.93 79.19 90 top
Q6103  DTA144VKAT146-GP  [SOT23-2D8-321H56]  170.89 17.59 270 top
Q6104  DTA144VKAT146-GP  [SOT23-2D8-321H56]  174.7 18.36 180 top
Q6201  DTA144VKAT146-GP  [SOT23-2D8-321H56]  196.03 86.81 0 top
Q6202  2N7002KDW-GP  [SOT-363H44]  125.42 97.1 90 bottom
Q6203  P8503BMG-GP  [SOT23DGS2D8H56]  133.3 67.25 0 top
Q7503  2N7002KDW-GP  [SOT-363H44]  181.05 111.19 0 bottom
Q7504  2N7002BK-GP  [SOT23DGS2D4H44]  184.99 117.92 0 bottom
R301  1KR2F-3-GP  [R402H16]  96.85 91.76 0 top
R302  1K69R2F-2-GP  [R402H16]  97.79 92.6 0 top
R401  150R2F-1-GP  [R402H16]  87.2 85.79 180 top
R402  2KR2F-3-GP  [R402H16]  81.73 82.62 90 bottom
R403  1KR2J-1-GP  [R402H16]  86.81 83.13 90 top
R404  0R0402-PAD-2-GP  [0R0402-PAD-1]  79.45 84.4 90 bottom
R405  75R2F-2-GP  [R402H16]  81.73 88.21 90 bottom
R406  75R2F-2-GP  [R402H16]  82.5 86.94 90 bottom
R407  499R2F-2-GP  [R402H16]  79.45 85.29 90 bottom
R408  75R2F-2-GP  [R402H16]  82.5 86.05 90 bottom
R409  0R2J-2-GP  [R402H16]  71.32 82.87 270 bottom
R410  1KR2J-1-GP  [R402H16]  77.16 76.01 180 bottom
R411  1KR2J-1-GP  [R402H16]  75.38 76.01 180 bottom
R412  0R0402-PAD-2-GP  [0R0402-PAD-1]  81.23 81.09 270 bottom
R413  1KR2J-1-GP  [R402H16]  76.27 76.01 180 bottom
R414  0R2J-2-GP  [R402H16]  71.91 85.92 90 bottom
R415  1KR2J-1-GP  [R402H16]  80.46 76.4 180 bottom
R416  1KR2J-1-GP  [R402H16]  79.58 76.4 180 bottom
R417  0R0402-PAD-2-GP  [0R0402-PAD-1]  85.29 79.32 90 top
R418  0R0402-PAD-2-GP  [0R0402-PAD-1]  70.18 85.92 270 bottom
R419  511R2F-2-GP  [R402H16]  81.23 80.21 90 bottom
R420  511R2F-2-GP  [R402H16]  80.59 79.32 90 bottom
R421  300R2J-4-GP  [R402H16]  71.32 81.98 270 bottom
R422  1KR2J-1-GP  [R402H16]  71.07 85.29 270 top
R423  1KR2J-1-GP  [R402H16]  71.07 86.12 270 top
R424  1KR2J-1-GP  [R402H16]  71.07 84.42 270 top
R425  1KR2J-1-GP  [R402H16]  71.07 83.58 270 top
R428  1KR2J-1-GP  [R402H16]  78.94 86.17 90 bottom
R434  1KR2J-1-GP  [R402H16]  78.81 79.32 90 bottom
R503  39D2R2F-L-GP  [R402H16]  100.02 72.59 0 top
R504  1KR2J-1-GP  [R402H16]  98.22 76.01 90 top
R601  10KR2J-3-GP  [R402H16]  115.26 76.65 270 bottom
R602  0R0402-PAD-2-GP  [0R0402-PAD-1]  112.85 93.29 90 bottom
R603  10KR2J-3-GP  [R402H16]  117.04 76.65 90 bottom
R604  10KR2J-3-GP  [R402H16]  115.26 77.54 270 bottom
R607  10KR2J-3-GP  [R402H16]  114.88 78.83 0 bottom
R608  10KR2J-3-GP  [R402H16]  112.85 88.59 270 bottom
R609  0R0402-PAD-2-GP  [0R0402-PAD-1]  114.5 85.03 90 bottom
R610  0R0402-PAD-2-GP  [0R0402-PAD-1]  115.26 75.76 90 bottom
R611  0R0402-PAD-2-GP  [0R0402-PAD-1]  124.91 83.25 180 top
R612  0R0402-PAD-2-GP  [0R0402-PAD-1]  107.13 99.51 180 bottom
R613  0R0402-PAD-2-GP  [0R0402-PAD-1]  106.25 99.51 180 bottom
R614  0R0402-PAD-2-GP  [0R0402-PAD-1]  105.36 99.51 180 bottom
R616  33R2J-2-GP  [R402H16]  108.02 99.51 0 bottom
R617  10KR2J-3-GP  [R402H16]  119.58 84.27 270 bottom
R618  0R0402-PAD-2-GP  [0R0402-PAD-1]  112.85 87.57 90 bottom
R620  10KR2J-3-GP  [R402H16]  113.99 92.4 270 bottom
R621  10KR2J-3-GP  [R402H16]  107.01 86.45 180 top
R622  0R2J-2-GP  [R402H16]  115.77 83.38 90 bottom
R623  20MR3-GP  [R603H22]  101.93 99.71 270 bottom
R625  0R0402-PAD-2-GP  [0R0402-PAD-1]  112.85 90.37 90 bottom
R626  100KR2J-1-GP  [R402H16]  115.77 84.65 0 bottom
R627  10KR2J-3-GP  [R402H16]  124.08 83.25 0 top
R628  1KR2J-1-GP  [R402H16]  121.38 91.23 90 top
R629  100KR2J-1-GP  [R402H16]  121.38 90.37 90 top
R630  10KR2J-3-GP  [R402H16]  112.85 89.48 270 bottom
R631  0R0402-PAD-2-GP  [0R0402-PAD-1]  119.58 79.85 270 bottom
R632  10KR2J-3-GP  [R402H16]  104.62 80.48 90 top
R633  10KR2J-3-GP  [R402H16]  103.58 99.51 0 bottom
R634  10KR2J-3-GP  [R402H16]  119.58 83.4 270 bottom
R635  10KR2J-3-GP  [R402H16]  117.04 77.54 90 bottom
R636  10KR2J-L-GP  [R402H15]  112.72 82.95 0 bottom
R637  10KR2J-L-GP  [R402H15]  115.77 78.83 180 bottom
R638  10KR2J-3-GP  [R402H16]  114.75 80.08 270 bottom
R639  10KR2J-3-GP  [R402H16]  113.99 82.87 270 bottom
R640  10KR2J-3-GP  [R402H16]  113.99 81.98 90 bottom
R641  10KR2J-3-GP  [R402H16]  113.74 81.09 90 bottom
R642  100KR2J-1-GP  [R402H16]  112.6 79.7 0 bottom
R643  100KR2J-1-GP  [R402H16]  113.48 79.7 180 bottom
R644  10KR2J-3-GP  [R402H16]  114.12 94.18 270 bottom
R645  15KR2J-1-GP  [R402H16]  112.85 91.38 90 bottom
R646  15KR2J-1-GP  [R402H16]  112.85 86.68 90 bottom
R647  15KR2J-1-GP  [R402H16]  122.37 85.29 0 top
R648  100KR2J-1-GP  [R402H16]  119.07 90.62 90 bottom
R649  10KR2J-3-GP  [R402H16]  115.39 92.02 0 bottom
R701  10KR2J-3-GP  [R402H16]  115.9 102.43 270 top
R702  10KR2J-3-GP  [R402H16]  111.07 102.94 90 top
R703  0R3J-0-U-GP  [R603H22]  103.07 83.38 0 top
R704  0R2J-2-GP  [R402H16]  117.17 102.68 0 top
R705  100KR2J-1-GP  [R402H16]  115.9 103.32 90 top
R706  100KR2J-1-GP  [R402H16]  114.12 103.32 270 top
R1901  0R0402-PAD-2-GP  [0R0402-PAD-1]  108.91 99.51 180 bottom
R1902  11K8R2F-GP  [R402H16]  101.5 92.68 270 top
R1903  1KR2F-3-GP  [R402H16]  106.3 83 180 top
R1904  1KR2F-3-GP  [R402H16]  104.47 83.02 180 top
R1905  1MR2J-1-GP  [R402H16]  93.93 97.22 90 bottom
R1906  0R0402-PAD-2-GP  [0R0402-PAD-1]  114.12 95.06 270 bottom
R1907  0R2J-2-GP  [R402H16]  116.15 100.53 0 bottom
R1908  0R0402-PAD-2-GP  [0R0402-PAD-1]  121.36 86.56 90 top
R1909  1KR2F-3-GP  [R402H16]  101.45 89.32 90 top
R1910  1KR2F-3-GP  [R402H16]  99.64 90.24 180 top
R1911  10KR2J-L-GP  [R402H15]  114.12 95.95 90 bottom
R1912  2KR2J-1-GP  [R402H16]  115.26 100.53 0 bottom
R1913  10KR2J-3-GP  [R402H16]  111.07 101.72 180 bottom
R1914  2KR2J-1-GP  [R402H16]  110.18 101.72 0 bottom
R1915  10KR2J-L-GP  [R402H15]  119.58 82.51 90 bottom
R1916  2KR2J-1-GP  [R402H16]  117.8 82.49 90 bottom
R1917  2KR2J-1-GP  [R402H16]  114.12 86.3 0 bottom
R1918  10KR2J-3-GP  [R402H16]  115.39 85.92 270 bottom
R1919  2KR2J-1-GP  [R402H16]  112.85 95.57 180 bottom
R1920  10KR2J-3-GP  [R402H16]  115.52 99.26 90 bottom
R1921  0R0402-PAD-2-GP  [0R0402-PAD-1]  121.36 87.44 90 top
R1922  0R0402-PAD-2-GP  [0R0402-PAD-1]  121.36 88.33 90 top
R1923  0R0402-PAD-2-GP  [0R0402-PAD-1]  117.04 89.35 270 bottom
R1924  0R0402-PAD-2-GP  [0R0402-PAD-1]  117.04 90.24 270 bottom
R1925  33R2J-2-GP  [R402H16]  121.36 89.22 90 top
R1926  2KR2J-1-GP  [R402H16]  115.64 89.98 180 bottom
R1927  10KR2J-L-GP  [R402H15]  114.75 89.98 180 bottom
R1928  2KR2J-1-GP  [R402H16]  108.18 82.82 0 top
R1929  10KR2J-L-GP  [R402H15]  109.01 82.82 0 top
R2401  10KR2J-3-GP  [R402H16]  181.68 26.51 90 top
R2402  0R0603-PAD-2-GP-U  [0R0603-PAD-1-U]  167.67 16.68 270 top
R2403  2D2R3-1-U-GP  [R603H22]  169.11 28.77 90 bottom
R2404  64K9R2F-1-GP  [R402H16]  163.52 19.37 90 top
R2405  27KR2F-L-GP  [R402H16]  159.85 20.55 270 top
R2406  100KR2F-L1-GP  [R402H16]  165.31 19.72 90 top
R2407  100KR2F-L1-GP  [R402H16]  159.41 22.49 0 top
R2408  0R0402-PAD-2-GP  [0R0402-PAD-1]  182.87 38.42 270 top
R2409  0R0402-PAD-2-GP  [0R0402-PAD-1]  177.11 27.12 180 bottom
R2410  0R0402-PAD-2-GP  [0R0402-PAD-1]  172.79 22.8 270 bottom
R2411  0R2J-2-GP  [R402H16]  177.62 25.72 90 bottom
R2412  10KR2J-3-GP  [R402H16]  173.05 27.88 0 bottom
R2413  100KR2J-1-GP  [R402H16]  157.35 33.83 0 top
R2414  10KR2J-3-GP  [R402H16]  158.82 29.28 270 top
R2415  10KR2J-3-GP  [R402H16]  179.82 42.35 180 top
R2416  0R0402-PAD-2-GP  [0R0402-PAD-1]  177.38 29.18 0 bottom
R2417  0R0402-PAD-2-GP  [0R0402-PAD-1]  182.46 37.06 0 top
R2418  10KR2J-3-GP  [R402H16]  157.76 27.25 180 top
R2419  0R0402-PAD-2-GP  [0R0402-PAD-1]  158.07 24.17 90 top
R2420  33R2J-2-GP  [R402H16]  158.07 23.28 90 top
